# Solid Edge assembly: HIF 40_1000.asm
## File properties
Title: Zylinder
Author: ahadarics
Template: iso assembly.asm
Last saved by: ahadarics
Revision: 95
Application: Solid Edge
Username: ahadarics
Dokumentum tartalom típus: 1
Document Number: HIF 40/1000
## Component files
Kit_2.par
Kit_1.par
Profilrohr 40_1000.par
Mutter.par
Kolbenstange 40_1000.par
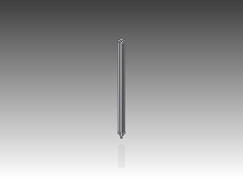
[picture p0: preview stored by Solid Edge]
